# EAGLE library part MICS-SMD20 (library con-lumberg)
CONNECTOR
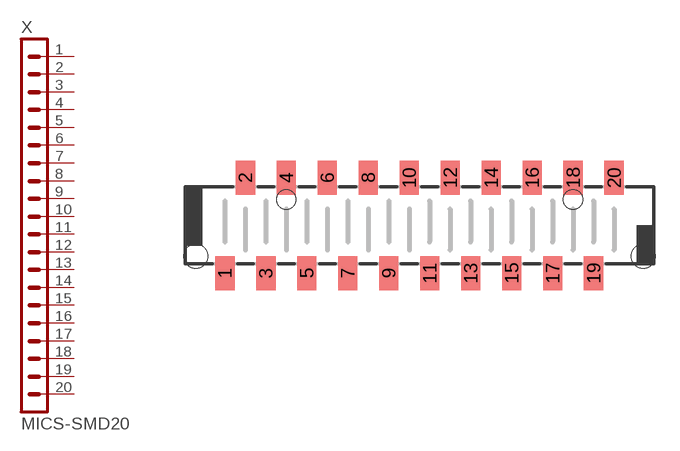
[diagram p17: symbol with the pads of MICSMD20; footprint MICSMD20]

Designator prefix X

## MICS-SMD20 (OC_FARNELL: unknown; OC_NEWARK: unknown)  [MICSMD20]
1  1  pas
2  2  pas
3  3  pas
4  4  pas
5  5  pas
6  6  pas
7  7  pas
8  8  pas
9  9  pas
10  10  pas
11  11  pas
12  12  pas
13  13  pas
14  14  pas
15  15  pas
16  16  pas
17  17  pas
18  18  pas
19  19  pas
20  20  pas

## Footprint MICSMD20 (pad centres in mm)
CONNECTOR
smd 1.2 x 2.1: 1 -12.065,-2.959; 2 -10.795,2.959; 3 -9.525,-2.959; 4 -8.255,2.959; 5 -6.985,-2.959; 6 -5.715,2.959; 7 -4.445,-2.959; 8 -3.175,2.959; 9 -1.905,-2.959; 10 -0.635,2.959; 11 0.635,-2.959; 12 1.905,2.959; 13 3.175,-2.959; 14 4.445,2.959; 15 5.715,-2.959; 16 6.985,2.959; 17 8.255,-2.959; 18 9.525,2.959; 19 10.795,-2.959; 20 12.065,2.959
hole 1.5 at 13.865,-1.912
hole 1.5 at -13.865,-1.912
hole 1.2 at -8.255,1.6
hole 1.2 at 9.525,1.6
